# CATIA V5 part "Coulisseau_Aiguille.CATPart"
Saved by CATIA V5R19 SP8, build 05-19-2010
Part number: Coulisseau_Aiguille
Bounding box of the stored display mesh (mm): x -15 to 3.5, y -12.5 to 12.5, z -131 to -77
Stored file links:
  C:\Users\ThinkMotion\Desktop\EU_thinkMotion\iao\IAO_MMS_Groupe3\pmayet\pmayet_avant_optimisation\pmayet_avant_optimisation\Coulisseau_Aiguille.CATPart
  C:\Users\ThinkMotion\Desktop\EU_thinkMotion\iao\IAO_MMS_Groupe3\pmayet\pmayet_avant_optimisation\pmayet_avant_optimisation\pmayet.CATProduct
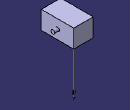
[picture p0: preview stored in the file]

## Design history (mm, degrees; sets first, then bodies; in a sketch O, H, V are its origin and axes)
Parameters
  Epaisseur_coulisseau = 15 mm
  Hauteur_coulisseau = 14 mm
  Largeur_coulisseau = 25 mm
  Rayon_axe = 1.5 mm
  Longueur_axe = 3.5 mm
  Longueur_aiguille = 40 mm
  Rayon_aiguille = 1.25 mm
  Hauteur_chas = 3 mm
  Distance_aiguille_bord_bati = 6 mm
  Rayon_chas = 0.3 mm
Set1
  Plane1: linked copy from another document
  Point1 "PointB": linked copy from another document
  Plane2: linked copy from another document
  Point2 "Point_origine_aiguille": linked copy from another document
Body1 (main body)
  Sketch1 on Plane1, origin (0, 0, 0), H (0, 1, 0), V (0, 0, 1)
    line L1 (-12.5, -77) -> (12.5, -77)
    line L2 (12.5, -77) -> (12.5, -91)
    line L3 (12.5, -91) -> (-12.5, -91)
    line L4 (-12.5, -91) -> (-12.5, -77)
    reference projected point E1 (0, -84) from Point1
    reference projected point E2 (0, -84) from Point1
    reference projected point E3 (0, -84) from Point1
    reference projected point E4 (0, -84) from Point1
    distance E1 L2 = 12.5 {= Largeur_coulisseau /2}
    distance E2 L4 = 12.5 {= Largeur_coulisseau /2}
    distance E3 L1 = 7 {= Hauteur_coulisseau /2}
    distance E4 L3 = 7 {= Hauteur_coulisseau /2}
    horizontal: L1 H, L3 H
    vertical: L2 V, L4 V
  Pad1: profile Sketch1, direction (-1, 0, 0), length 15 {= Epaisseur_coulisseau}
  Sketch2 on Plane1, origin (0, 0, 0), H (0, 1, 0), V (0, 0, 1)
    circle A1 centre (0, -84) radius 1.5
    point P1 (0, -84)
    reference projected point E1 (0, -84) from Point1
    distance A1 P1 = 1.5 {= Rayon_axe}
    coincidence: E1 P1
  Pad2: profile Sketch2, direction (1, 0, 0), length 3.5 {= Longueur_axe}
  Sketch3 on Plane2, origin (-6, 0, 0), H (0, 1, 0), V (0, 0, 1)
    line L1 (5.875, -84) -> (5.875, -129)
    point P1 (5.875, -84)
    point P2 (5.875, -129)
    line L2 (5.875, -84) -> (6.5, -84)
    point P3 (5.875, -84)
    point P4 (6.5, -84)
    line L3 (6.5, -84) -> (6.5, -131)
    point P5 (6.5, -84)
    point P6 (6.5, -131)
    reference projected point E1 (6.5, -84) from Point2
    line L4 (5.875, -129) -> (6.5, -131)
    point P7 (5.875, -129)
    point P8 (6.5, -131)
    axis line L5 (6.5, -106.5363) -> (6.5, -148)
    point P9 (6.5, -106.5363)
    reference projected point E2 (6.5, -84) from Point2
    length L3 = 47 {= Longueur_aiguille + Hauteur_coulisseau /2}
    length L1 = 45 {= Hauteur_coulisseau /2 +Longueur_aiguille -2mm}
    length L2 = 0.625 {= Rayon_aiguille /2}
    vertical: L1 V, L3 V, L5 V
    horizontal: L2 H
    coincidence: P1 P3, P5 P4, E1 L2, P7 P2, P8 P6, P9 L3, E2 L3
  Shaft1: profile Sketch3, axis Sketch3.L5, angle 360
  Sketch4 on Plane2, origin (-6, 0, 0), H (0, 1, 0), V (0, 0, 1)
    point P1 (6.5, -125.5)
    ellipse A1 centre (6.5, -125.5) semi-axes 1.5, 0.3 rotation 90
    reference projected line E1 through (6.5, 0) direction (0, -1) from axis of face of Shaft1 from Sketch3.L1
    reference projected line E2 (7.125, -129) -> (5.875, -129) from edge [face of Shaft1 from Sketch3.L1 | face of Shaft1 from Sketch3.L4]
    "Radius" A1 = 1.5 {= Hauteur_chas /2}
    "Radius" A1 = 0.3 {= Rayon_chas}
    distance E1 P1 = 0
    distance E2 P1 = 3.5
  Pocket1: profile Sketch4, direction (-1, 0, 0), length 3.5, mirrored extent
